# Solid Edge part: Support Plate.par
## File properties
Author: Dan
Template: metric part.par
Last saved by: Dan
Revision: 27
Application: Solid Edge
Material: Steel
Face Style: Steel
Fill Style: ANSI32(Steel)
Virtual Style: Machined steel
Coef. of Thermal Exp: 1.3e-05
Thermal Conductivity: 32.0
Specific Heat: 481.0
Modulus of Elasticity: 199947953000.0
Poisson's Ratio: 0.29
Yield Stress: 262000766.0
Ultimate Stress: 358527364.0
Elongation: 0.0
Density: 7833.000 kg/m^3
Accuracy: 0.990
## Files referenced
..\Moving Half.asm
C:\Drawing Files Other\Dave\Tente\HUP 125X36H45-TSA 02-07-2011\Wheel Mould\MH Die Plate.par
C:\Drawing Files Other\Dave\Tente\HUP 125X36H45-TSA 02-07-2011\Wheel Mould\MH insert Outer.par
C:\Drawing Files Other\Dave\Tente\HUP 125X36H45-TSA 02-07-2011\Wheel Mould\MH Sleeve.par
C:\Drawing Files Other\Dave\Tente\HUP 125X36H45-TSA 02-07-2011\Wheel Mould\Riser.par
ZC:\Drawing Files Other\Dave\Tente\HUP 125X36H45-TSA 02-07-2011\Wheel Mould\Moving Half.asm
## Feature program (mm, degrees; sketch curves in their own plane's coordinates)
sketch for "unnamed Protrusion 1" plane through (0, 0, 0) normal (0, 0, 1) x-axis (1, 0, 0)
  hole centre (-170, 170) bore radius 17.5
extrude "unnamed Protrusion 1" add finite 46 along -normal
sketch for "unnamed Cutout 1" #1 plane through (0, 0, -46) normal (0, 0, -1) x-axis (1, 0, 0)
sketch for "unnamed Cutout 1" #2 plane through (0, 0, -46) normal (0, 0, -1) x-axis (1, 0, 0)
  circle centre (-75, 75) radius 19.75
sketch for "unnamed Cutout 1" #3 plane through (0, 0, -46) normal (0, 0, -1) x-axis (1, 0, 0)
  circle centre (75, 75) radius 19.75
sketch for "unnamed Cutout 1" #4 plane through (0, 0, -46) normal (0, 0, -1) x-axis (1, 0, 0)
extrude "unnamed Cutout 1" cut through along -normal
sketch for "Hole_13" plane through (0, 0, -46) normal (0, 0, -1) x-axis (1, 0, 0)
hole "Hole_13" diameter 10 through  VBottomAngle = 118 deg
sketch for "unnamed Hole 1" plane through (0, 0, -46) normal (0, 0, -1) x-axis (1, 0, 0)
  hole centre (75, 170) bore radius 5
hole "unnamed Hole 1" through
sketch for "unnamed Hole 2" plane through (0, 0, -46) normal (0, 0, -1) x-axis (1, 0, 0)
  hole centre (75, -170) bore radius 5
hole "unnamed Hole 2" through
sketch for "unnamed Hole 3" plane through (0, 0, -46) normal (0, 0, -1) x-axis (1, 0, 0)
  hole centre (-75, -170) bore radius 5
hole "unnamed Hole 3" through
sketch for "Hole_17" plane through (0, 0, -46) normal (0, 0, -1) x-axis (1, 0, 0)
  hole centre (-58.916, -35.1552) bore radius 3.25
hole "Hole_17" diameter 6.5 through  CounterBoreDepth = 6.5 mm
sketch for "unnamed Hole 4" plane through (0, 0, -46) normal (0, 0, -1) x-axis (1, 0, 0)
  hole centre (-114.893, -58.916) bore radius 3.25
hole "unnamed Hole 4" through
sketch for "unnamed Hole 5" plane through (0, 0, -46) normal (0, 0, -1) x-axis (1, 0, 0)
  hole centre (-91.1322, -114.893) bore radius 3.25
hole "unnamed Hole 5" through
sketch for "unnamed Hole 6" plane through (0, 0, -46) normal (0, 0, -1) x-axis (1, 0, 0)
  hole centre (-35.1552, -91.1322) bore radius 3.25
hole "unnamed Hole 6" through
sketch for "unnamed Hole 7" plane through (0, 0, -46) normal (0, 0, -1) x-axis (1, 0, 0)
  hole centre (35.107, -58.916) bore radius 3.25
hole "unnamed Hole 7" through
sketch for "unnamed Hole 8" plane through (0, 0, -46) normal (0, 0, -1) x-axis (1, 0, 0)
  hole centre (91.084, -35.1552) bore radius 3.25
hole "unnamed Hole 8" through
sketch for "unnamed Hole 9" plane through (0, 0, -46) normal (0, 0, -1) x-axis (1, 0, 0)
  hole centre (114.8448, -91.1322) bore radius 3.25
hole "unnamed Hole 9" through
sketch for "unnamed Hole 10" plane through (0, 0, -46) normal (0, 0, -1) x-axis (1, 0, 0)
  hole centre (58.8678, -114.893) bore radius 3.25
hole "unnamed Hole 10" through
sketch for "unnamed Hole 11" plane through (0, 0, -46) normal (0, 0, -1) x-axis (1, 0, 0)
  hole centre (35.107, 91.084) bore radius 3.25
hole "unnamed Hole 11" through
sketch for "unnamed Hole 12" plane through (0, 0, -46) normal (0, 0, -1) x-axis (1, 0, 0)
  hole centre (91.084, 114.8448) bore radius 3.25
hole "unnamed Hole 12" through
sketch for "unnamed Hole 13" plane through (0, 0, -46) normal (0, 0, -1) x-axis (1, 0, 0)
  hole centre (114.8448, 58.8678) bore radius 3.25
hole "unnamed Hole 13" through
sketch for "unnamed Hole 14" plane through (0, 0, -46) normal (0, 0, -1) x-axis (1, 0, 0)
  hole centre (58.8678, 35.107) bore radius 3.25
hole "unnamed Hole 14" through
sketch for "unnamed Hole 15" plane through (0, 0, -46) normal (0, 0, -1) x-axis (1, 0, 0)
  hole centre (-58.916, 114.8448) bore radius 3.25
hole "unnamed Hole 15" through
sketch for "unnamed Hole 16" plane through (0, 0, -46) normal (0, 0, -1) x-axis (1, 0, 0)
  hole centre (-35.1552, 58.8678) bore radius 3.25
hole "unnamed Hole 16" through
sketch for "unnamed Hole 17" plane through (0, 0, -46) normal (0, 0, -1) x-axis (1, 0, 0)
  hole centre (-91.1322, 35.107) bore radius 3.25
hole "unnamed Hole 17" through
sketch for "unnamed Hole 18" plane through (0, 0, -46) normal (0, 0, -1) x-axis (1, 0, 0)
  hole centre (-114.893, 91.084) bore radius 3.25
hole "unnamed Hole 18" through
sketch for "unnamed Cutout 2" #1 plane through (0, 0, -46) normal (0, 0, -1) x-axis (1, 0, 0)
sketch for "unnamed Cutout 2" #2 plane through (0, 0, -46) normal (0, 0, -1) x-axis (1, 0, 0)
sketch for "unnamed Cutout 2" #3 plane through (0, 0, -46) normal (0, 0, -1) x-axis (1, 0, 0)
  circle centre (-170, -106) radius 10
sketch for "unnamed Cutout 2" #4 plane through (0, 0, -46) normal (0, 0, -1) x-axis (1, 0, 0)
  circle centre (170, -106) radius 10
extrude "unnamed Cutout 2" cut through along -normal
sketch for "unnamed Cutout 3" #1 plane through (0, 0, -46) normal (0, 0, -1) x-axis (1, 0, 0)
sketch for "unnamed Cutout 3" #2 plane through (0, 0, -46) normal (0, 0, -1) x-axis (1, 0, 0)
sketch for "unnamed Cutout 3" #3 plane through (0, 0, -46) normal (0, 0, -1) x-axis (1, 0, 0)
  circle centre (-170, 0) radius 6.25
sketch for "unnamed Cutout 3" #4 plane through (0, 0, -46) normal (0, 0, -1) x-axis (1, 0, 0)
  circle centre (-170, -139) radius 6.25
sketch for "unnamed Cutout 3" #5 plane through (0, 0, -46) normal (0, 0, -1) x-axis (1, 0, 0)
  circle centre (75, -75) radius 19.75
sketch for "unnamed Cutout 3" #6 plane through (0, 0, -46) normal (0, 0, -1) x-axis (1, 0, 0)
extrude "unnamed Cutout 3" cut through along -normal
sketch for "Hole_33" plane through (0, 0, -46) normal (0, 0, -1) x-axis (-1, 0, 0)
hole "Hole_33" diameter 35 through  VBottomAngle = 118 deg
sketch for "unnamed Hole 19" plane through (0, 0, -46) normal (0, 0, -1) x-axis (-1, 0, 0)
hole "unnamed Hole 19" through
sketch for "unnamed Hole 20" plane through (0, 0, -46) normal (0, 0, -1) x-axis (-1, 0, 0)
  hole centre (170, -170) bore radius 17.5
hole "unnamed Hole 20" through
sketch for "unnamed Hole 21" plane through (0, 0, -46) normal (0, 0, -1) x-axis (-1, 0, 0)
hole "unnamed Hole 21" through
pattern "unnamed Pattern 1" of "Hole_33", "unnamed Hole 19", "unnamed Hole 20", "unnamed Hole 21"
sketch for "Hole_37" plane through (0, 0, -46) normal (0, 0, -1) x-axis (-1, 0, 0)
hole "Hole_37" diameter 8 finite  VBottomAngle = 118 deg
sketch for "unnamed Hole 22" plane through (0, 0, -46) normal (0, 0, -1) x-axis (-1, 0, 0)
hole "unnamed Hole 22" finite
pattern "unnamed Pattern 2" of "Hole_37", "unnamed Hole 22"
sketch for "Hole_39" plane through (0, 0, 0) normal (0, 0, 1) x-axis (1, 0, 0)
hole "Hole_39" diameter 27 through  VBottomAngle = 118 deg
sketch for "unnamed Hole 23" plane through (0, 0, 0) normal (0, 0, 1) x-axis (1, 0, 0)
hole "unnamed Hole 23" through
sketch for "unnamed Hole 24" plane through (0, 0, 0) normal (0, 0, 1) x-axis (1, 0, 0)
  hole centre (75, -170) bore radius 13.5
hole "unnamed Hole 24" through
sketch for "unnamed Hole 25" plane through (0, 0, 0) normal (0, 0, 1) x-axis (1, 0, 0)
  hole centre (-75, -170) bore radius 13.5
hole "unnamed Hole 25" through
pattern "unnamed Pattern 3" of "Hole_39", "unnamed Hole 23", "unnamed Hole 24", "unnamed Hole 25"
pattern "unnamed Pattern 4" of "Hole_13", "unnamed Hole 1", "unnamed Hole 2", "unnamed Hole 3"
pattern "unnamed Pattern 5" of "Hole_17", "unnamed Hole 4", "unnamed Hole 5", "unnamed Hole 6", "unnamed Hole 7", "unnamed Hole 8", "unnamed Hole 9", "unnamed Hole 10", "unnamed Hole 11", "unnamed Hole 12", "unnamed Hole 13", "unnamed Hole 14"
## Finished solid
Body 1: solid body, 80 faces, 124 edges, 8 vertices.
  Faces by surface: cylinder 56, plane 22, cone 2
  Edges by curve: circle 112, line 12
Bounding box of the edges (mm): 396.000 x 396.000 x 46.000, from (-198, -198, -46) to (198, 198, 0).
Cylindrical faces by radius (mm): R3.25 x16, R3.3235 x2, R6 x16, R6.25 x6, R10 x4, R13.5 x4, R17.5 x4, R19.75 x4
Conical faces (half-angle, radius in mm at the cone's reference point): 59 deg R3.3235 x2
Planar faces by outward normal: +x 1, +y 1, +z 1, -x 1, -y 1, -z 17
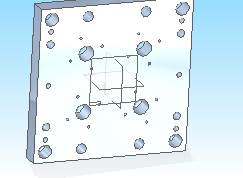
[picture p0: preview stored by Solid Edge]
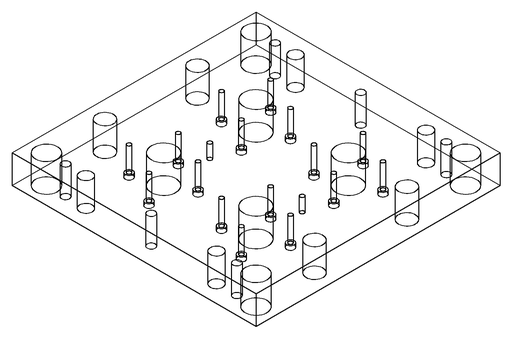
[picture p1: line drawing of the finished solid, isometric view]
